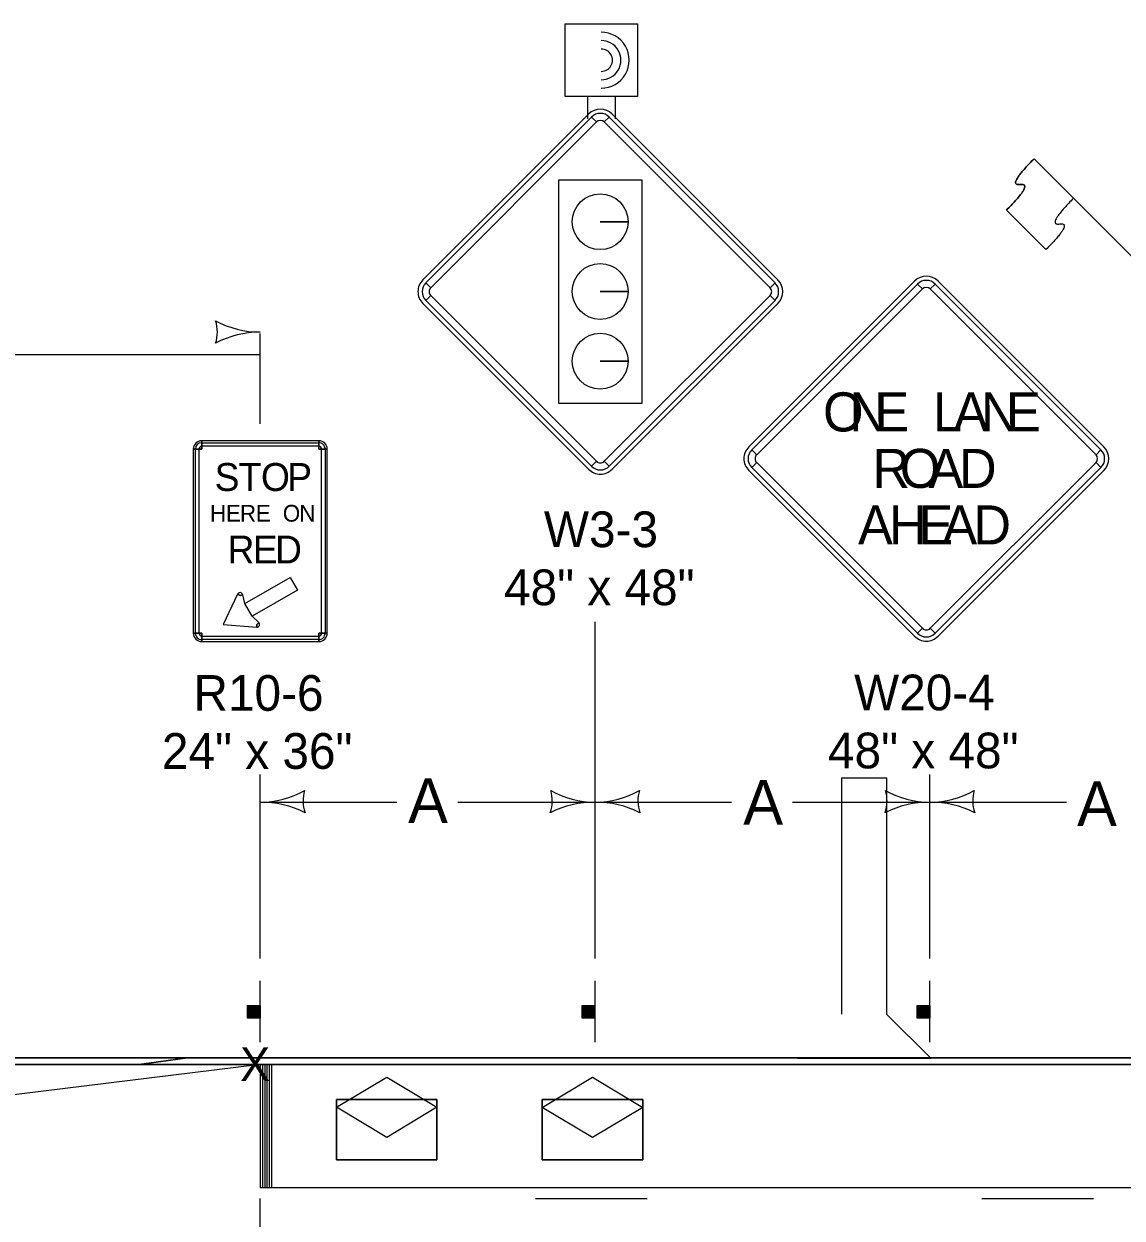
# Model space of a CAD drawing. Extents: x 10133 to 81668, y 4692 to 11018.
# Drawn here: x 23247 to 23739, y 6856 to 7391 of the extents above; entities that cross this region are included whole.
import ezdxf

# ---------------------------------------------------------------- set-up
doc = ezdxf.new("R2010")
doc.units = 0
for name, color, linetype in [('dsnCellElements', 7, 'Continuous'), ('dsnTextTabulation', 7, 'Continuous'), ('Level 5', 7, 'Continuous'), ('Level 8', 7, 'Continuous'), ('SheetAddendum', 7, 'Continuous'), ('SheetBorder', 7, 'Continuous'), ('ShtPlotIdentification', 7, 'Continuous')]:
    doc.layers.add(name, color=color, linetype=linetype)

msp = doc.modelspace()

# ---------------------------------------------------------------- linework, layer by layer
at = {"layer": 'dsnCellElements'}
for p, q in [((23499.06, 7358.55), (23499.06, 7348.55)), ((23511.56, 7358.55), (23511.56, 7348.55)), ((23352.53, 7211.87), (23352.53, 7252.28)), ((22734.47, 7242.98), (23352.53, 7242.98)), ((23502.53, 6972.3), (23502.53, 7123.21)), ((23352.53, 6972.3), (23352.53, 7054.8)), ((23652.53, 6972.3), (23652.53, 7054.8)), ((23352.53, 7042.3), (23413.7, 7042.3)), ((23441.03, 7042.3), (23502.53, 7042.3)), ((23502.53, 7042.3), (23563.7, 7042.3)), ((23591.03, 7042.3), (23652.53, 7042.3)), ((23652.53, 7042.3), (23713.7, 7042.3)), ((23352.53, 6934.8), (23352.53, 6962.3)), ((23502.53, 6934.8), (23502.53, 6962.3)), ((23652.53, 6934.8), (23652.53, 6962.3)), ((23347.2, 6945.67), (23347.2, 6951.25)), ((23347.52, 6951.25), (23347.52, 6945.67)), ((23347.75, 6945.67), (23347.75, 6951.25)), ((23348.06, 6951.25), (23348.06, 6945.67)), ((23348.29, 6945.67), (23348.27, 6951.25)), ((23348.7, 6951.25), (23348.72, 6945.67)), ((23348.93, 6945.67), (23348.93, 6951.25)), ((23349.36, 6951.25), (23349.36, 6945.67)), ((23349.73, 6945.67), (23349.73, 6951.25)), ((23350.05, 6951.25), (23350.07, 6945.67)), ((23350.28, 6945.67), (23350.28, 6951.25)), ((23350.54, 6951.25), (23350.54, 6945.67)), ((23350.88, 6945.67), (23350.88, 6951.25)), ((23351.08, 6951.25), (23351.08, 6945.67)), ((23351.31, 6945.67), (23351.31, 6951.25)), ((23351.57, 6951.25), (23351.57, 6945.67)), ((23351.83, 6945.67), (23351.83, 6951.25)), ((23352.11, 6951.25), (23352.11, 6945.67)), ((23497.2, 6945.67), (23497.2, 6951.25)), ((23497.52, 6951.25), (23497.52, 6945.67)), ((23497.75, 6945.67), (23497.75, 6951.25)), ((23498.06, 6951.25), (23498.06, 6945.67)), ((23498.29, 6945.67), (23498.27, 6951.25)), ((23498.7, 6951.25), (23498.72, 6945.67)), ((23498.93, 6945.67), (23498.93, 6951.25)), ((23499.36, 6951.25), (23499.36, 6945.67)), ((23499.73, 6945.67), (23499.73, 6951.25)), ((23500.05, 6951.25), (23500.07, 6945.67)), ((23500.28, 6945.67), (23500.28, 6951.25)), ((23500.54, 6951.25), (23500.54, 6945.67)), ((23500.88, 6945.67), (23500.88, 6951.25)), ((23501.08, 6951.25), (23501.08, 6945.67)), ((23501.31, 6945.67), (23501.31, 6951.25)), ((23501.57, 6951.25), (23501.57, 6945.67)), ((23501.83, 6945.67), (23501.83, 6951.25)), ((23502.11, 6951.25), (23502.11, 6945.67)), ((23647.2, 6945.67), (23647.2, 6951.25)), ((23647.52, 6951.25), (23647.52, 6945.67)), ((23647.75, 6945.67), (23647.75, 6951.25)), ((23648.06, 6951.25), (23648.06, 6945.67)), ((23648.29, 6945.67), (23648.27, 6951.25)), ((23648.7, 6951.25), (23648.72, 6945.67)), ((23648.93, 6945.67), (23648.93, 6951.25)), ((23649.36, 6951.25), (23649.36, 6945.67)), ((23649.73, 6945.67), (23649.73, 6951.25)), ((23650.05, 6951.25), (23650.07, 6945.67)), ((23650.28, 6945.67), (23650.28, 6951.25)), ((23650.54, 6951.25), (23650.54, 6945.67)), ((23650.88, 6945.67), (23650.88, 6951.25)), ((23651.08, 6951.25), (23651.08, 6945.67)), ((23651.31, 6945.67), (23651.31, 6951.25)), ((23651.57, 6951.25), (23651.57, 6945.67)), ((23651.83, 6945.67), (23651.83, 6951.25)), ((23652.11, 6951.25), (23652.11, 6945.67)), ((24004.98, 6924.8), (22692.53, 6924.8)), ((23352.53, 6924.8), (22864.67, 6864.81)), ((23352.53, 6924.8), (23352.53, 6869.8)), ((23353.53, 6924.8), (23353.53, 6869.8)), ((23354.53, 6924.8), (23354.53, 6869.8)), ((23355.53, 6924.8), (23355.53, 6869.8)), ((23356.53, 6924.8), (23356.53, 6869.8)), ((23357.53, 6924.8), (23357.53, 6869.8)), ((23386.69, 6882.18), (23386.69, 6909.18)), ((23386.69, 6909.18), (23431.69, 6909.18)), ((23386.69, 6882.18), (23386.69, 6909.18)), ((23386.69, 6909.18), (23431.69, 6909.18)), ((23431.69, 6909.18), (23386.69, 6909.18)), ((23386.69, 6909.18), (23386.69, 6882.18)), ((23431.69, 6882.18), (23431.69, 6909.18)), ((23431.69, 6909.18), (23431.69, 6882.18)), ((23431.69, 6882.18), (23431.69, 6909.18)), ((23478.88, 6882.1), (23478.88, 6909.1)), ((23478.88, 6909.1), (23523.88, 6909.1)), ((23478.88, 6882.1), (23478.88, 6909.1)), ((23478.88, 6909.1), (23523.88, 6909.1)), ((23523.88, 6909.1), (23478.88, 6909.1)), ((23478.88, 6909.1), (23478.88, 6882.1)), ((23523.88, 6882.1), (23523.88, 6909.1)), ((23523.88, 6909.1), (23523.88, 6882.1)), ((23523.88, 6882.1), (23523.88, 6909.1)), ((23386.69, 6882.18), (23431.69, 6882.18)), ((23431.69, 6882.18), (23386.69, 6882.18)), ((23386.69, 6882.18), (23431.69, 6882.18)), ((23478.88, 6882.1), (23523.88, 6882.1)), ((23523.88, 6882.1), (23478.88, 6882.1)), ((23478.88, 6882.1), (23523.88, 6882.1)), ((23352.53, 6627.2), (23352.53, 6864.8))]:
    msp.add_line(p, q, dxfattribs=at)
for points in [[(23489.06, 7358.55), (23489.06, 7391.05), (23521.56, 7391.05), (23521.56, 7358.55)], [(23352.43, 6951.25), (23352.43, 6945.63), (23346.81, 6945.63), (23346.81, 6951.25)], [(23502.43, 6951.25), (23502.43, 6945.63), (23496.81, 6945.63), (23496.81, 6951.25)], [(23652.43, 6951.25), (23652.43, 6945.63), (23646.81, 6945.63), (23646.81, 6951.25)]]:
    msp.add_lwpolyline(points, close=True, dxfattribs=at)
for centre, radius, start, end in [((23505.32, 7374.79), 12.5, 269.4041, 90.5445), ((23505.32, 7374.79), 12.5, 269.4041, 90.5445), ((23505.32, 7374.79), 8.75, 269.4041, 90.5445), ((23505.32, 7374.79), 5, 269.4041, 90.5445), ((23351.77, 7084.8), 42.5, 271.0176, 299.0725), ((23388.14, 7042.93), 16.42, 163.2666, 198.7334), ((23466.91, 7042.93), 16.42, 341.2666, 16.7334), ((23503.28, 7084.8), 42.5, 240.9275, 268.9824), ((23501.77, 7084.8), 42.5, 271.0176, 299.0725), ((23538.14, 7042.93), 16.42, 163.2666, 198.7334), ((23616.91, 7042.93), 16.42, 341.2666, 16.7334), ((23653.28, 7084.8), 42.5, 240.9275, 268.9824), ((23651.77, 7084.8), 42.5, 271.0176, 299.0725), ((23688.14, 7042.93), 16.42, 163.2666, 198.7334), ((23353.26, 6999.81), 42.5, 62.9275, 90.9824), ((23501.8, 6999.81), 42.5, 89.0176, 117.0725), ((23503.26, 6999.81), 42.5, 62.9275, 90.9824), ((23651.8, 6999.81), 42.5, 89.0176, 117.0725), ((23653.26, 6999.81), 42.5, 62.9275, 90.9824)]:
    msp.add_arc(centre, radius, start, end, dxfattribs=at)
at = {"layer": 'dsnTextTabulation'}
for p, q in [((23005.34, 6924.8), (23298.28, 6924.8)), ((23319.96, 6927.8), (23006.31, 6927.8)), ((23319.96, 6927.8), (23298.28, 6924.8)), ((23298.28, 6924.8), (23319.96, 6927.8)), ((23298.28, 6924.8), (23352.53, 6924.8)), ((24004.98, 6927.8), (23319.96, 6927.8)), ((23357.53, 6924.8), (24004.98, 6924.8)), ((23352.53, 6869.8), (23802.53, 6869.8)), ((23475.82, 6864.8), (23525.82, 6864.8)), ((23675.82, 6864.8), (23675.82, 6864.8)), ((23675.82, 6864.8), (23725.82, 6864.8))]:
    msp.add_line(p, q, dxfattribs=at)
for points in [[(22692.53, 6927.8), (24004.98, 6927.8)], [(22692.53, 6924.8), (24004.98, 6924.8)], [(23352.53, 6924.8), (23353.53, 6924.8), (23354.53, 6924.8)], [(23354.53, 6924.8), (23355.53, 6924.8), (23356.53, 6924.8), (23357.53, 6924.8)]]:
    msp.add_lwpolyline(points, dxfattribs=at)
at = {"layer": 'Level 5'}
msp.add_line((23686.8, 7307.59), (23704.48, 7289.92), dxfattribs=at)
for points in [[(23699.17, 7330.59), (23686.8, 7318.2), (23699.18, 7319.97), (23686.8, 7307.59)], [(23716.86, 7312.91), (23704.49, 7300.52), (23716.86, 7302.3), (23704.48, 7289.92)]]:
    msp.add_open_spline(points, degree=2, dxfattribs=at)
at = {"layer": 'Level 8'}
for centre, radius, start, end in [((23316.89, 7252.98), 16.42, 342.2666, 17.7333), ((23352.52, 7295.48), 42.5, 241.9275, 270), ((23352.52, 7210.48), 42.5, 90, 118.0725)]:
    msp.add_arc(centre, radius, start, end, dxfattribs=at)
at = {"layer": 'SheetAddendum'}
for p, q in [((23499.6, 7350.64), (23425.35, 7276.39)), ((23500.93, 7349.31), (23503.13, 7347.1)), ((23506.67, 7347.1), (23508.88, 7349.31)), ((23584.45, 7276.39), (23510.21, 7350.64)), ((23756.51, 7273.29), (23699.17, 7330.59)), ((23699.17, 7330.59), (23716.86, 7312.91)), ((23704.48, 7289.92), (23686.8, 7307.59)), ((23517.31, 7302.42), (23504.81, 7302.42)), ((23504.81, 7302.42), (23517.31, 7302.42)), ((23428.89, 7272.86), (23426.68, 7275.07)), ((23517.31, 7271.17), (23504.81, 7271.17)), ((23504.81, 7271.17), (23517.31, 7271.17)), ((23645.64, 7275.82), (23571.39, 7201.57)), ((23583.13, 7275.07), (23580.92, 7272.86)), ((23646.96, 7274.49), (23649.17, 7272.28)), ((23652.71, 7272.28), (23654.92, 7274.49)), ((23730.49, 7201.57), (23656.24, 7275.82)), ((23425.35, 7265.79), (23499.6, 7191.54)), ((23426.68, 7267.11), (23428.89, 7269.32)), ((23510.21, 7191.54), (23584.45, 7265.79)), ((23580.92, 7269.32), (23583.13, 7267.11)), ((23517.31, 7239.92), (23504.81, 7239.92)), ((23504.81, 7239.92), (23517.31, 7239.92)), ((23326.28, 7200.55), (23326.28, 7204.3)), ((23326.28, 7201.8), (23326.28, 7203.36)), ((23378.78, 7204.3), (23378.78, 7200.55)), ((23378.78, 7203.36), (23378.78, 7201.8)), ((23322.53, 7200.55), (23326.28, 7200.55)), ((23323.46, 7200.55), (23325.03, 7200.55)), ((23378.78, 7200.55), (23382.53, 7200.55)), ((23380.03, 7200.55), (23381.59, 7200.55)), ((23574.92, 7198.04), (23572.72, 7200.25)), ((23729.16, 7200.25), (23726.95, 7198.04)), ((23503.13, 7195.07), (23500.93, 7192.86)), ((23508.88, 7192.86), (23506.67, 7195.07)), ((23571.39, 7190.97), (23645.64, 7116.72)), ((23572.72, 7192.29), (23574.92, 7194.5)), ((23656.24, 7116.72), (23730.49, 7190.97)), ((23726.95, 7194.5), (23729.16, 7192.29)), ((23342.38, 7135.57), (23343.49, 7134.99)), ((23343.49, 7134.99), (23344.71, 7135.26)), ((23350.99, 7122), (23350.94, 7120.75)), ((23351.84, 7122.92), (23350.99, 7122)), ((23326.28, 7118.05), (23322.53, 7118.05)), ((23325.03, 7118.05), (23323.46, 7118.05)), ((23326.28, 7114.3), (23326.28, 7118.05)), ((23326.28, 7115.24), (23326.28, 7116.8)), ((23382.53, 7118.05), (23378.78, 7118.05)), ((23378.78, 7118.05), (23378.78, 7114.3)), ((23378.78, 7116.8), (23378.78, 7115.24)), ((23381.59, 7118.05), (23380.03, 7118.05)), ((23649.17, 7120.26), (23646.96, 7118.05)), ((23654.92, 7118.05), (23652.71, 7120.26))]:
    msp.add_line(p, q, dxfattribs=at)
for points in [[(23500.93, 7349.31), (23426.68, 7275.07), (23428.89, 7272.86), (23503.13, 7347.1), (23500.93, 7349.31)], [(23583.13, 7275.07), (23508.88, 7349.31), (23506.67, 7347.1), (23580.92, 7272.86), (23583.13, 7275.07)], [(23523.63, 7321.03), (23486.17, 7321.03), (23486.17, 7221.14), (23523.63, 7221.14), (23523.63, 7321.03)], [(23646.96, 7274.49), (23572.72, 7200.25), (23574.92, 7198.04), (23649.17, 7272.28), (23646.96, 7274.49)], [(23729.16, 7200.25), (23654.92, 7274.49), (23652.71, 7272.28), (23726.95, 7198.04), (23729.16, 7200.25)], [(23426.68, 7267.11), (23500.93, 7192.86), (23503.13, 7195.07), (23428.89, 7269.32), (23426.68, 7267.11)], [(23508.88, 7192.86), (23583.13, 7267.11), (23580.92, 7269.32), (23506.67, 7195.07), (23508.88, 7192.86)], [(23326.28, 7114.3), (23378.78, 7114.3), (23378.78, 7118.05), (23382.53, 7118.05), (23382.53, 7200.55), (23378.78, 7200.55), (23378.78, 7204.3), (23326.28, 7204.3), (23326.28, 7200.55), (23322.53, 7200.55), (23322.53, 7118.05), (23326.28, 7118.05), (23326.28, 7114.3)], [(23378.78, 7201.8), (23326.28, 7201.8), (23326.28, 7203.36), (23378.78, 7203.36), (23378.78, 7201.8)], [(23325.03, 7200.55), (23325.03, 7118.05), (23323.46, 7118.05), (23323.46, 7200.55), (23325.03, 7200.55)], [(23380.03, 7118.05), (23380.03, 7200.55), (23381.59, 7200.55), (23381.59, 7118.05), (23380.03, 7118.05)], [(23572.72, 7192.29), (23646.96, 7118.05), (23649.17, 7120.26), (23574.92, 7194.5), (23572.72, 7192.29)], [(23654.92, 7118.05), (23729.16, 7192.29), (23726.95, 7194.5), (23652.71, 7120.26), (23654.92, 7118.05)], [(23365.9, 7143.05), (23369.18, 7137.37), (23348.87, 7125.64), (23345.59, 7131.33), (23365.9, 7143.05)], [(23335.87, 7121.93), (23350.94, 7120.75), (23350.99, 7122), (23351.84, 7122.92), (23348.87, 7125.64), (23345.59, 7131.33), (23344.71, 7135.26), (23343.49, 7134.99), (23342.38, 7135.57), (23335.87, 7121.93)], [(23326.28, 7116.8), (23378.78, 7116.8), (23378.78, 7115.24), (23326.28, 7115.24), (23326.28, 7116.8)]]:
    msp.add_lwpolyline(points, close=True, dxfattribs=at)
for centre in [(23504.81, 7302.42), (23504.81, 7271.17), (23504.81, 7239.92)]:
    msp.add_circle(centre, 12.5, dxfattribs=at)
for centre, radius, start, end in [((23504.9, 7345.33), 7.5, 45, 134.9997), ((23504.9, 7345.33), 5.62, 45, 134.9997), ((23504.9, 7345.33), 2.5, 45, 134.9997), ((23650.94, 7270.52), 7.5, 45, 134.9997), ((23430.66, 7271.09), 7.5, 134.9997, 225), ((23430.66, 7271.09), 5.62, 134.9997, 225), ((23430.66, 7271.09), 2.5, 134.9997, 225), ((23579.15, 7271.09), 2.5, 315.0002, 44.9998), ((23579.15, 7271.09), 5.62, 315.0002, 44.9998), ((23579.15, 7271.09), 7.5, 315.0002, 44.9998), ((23650.94, 7270.52), 5.62, 45, 134.9997), ((23650.94, 7270.52), 2.5, 45, 134.9997), ((23326.28, 7200.55), 3.75, 90.0002, 179.9998), ((23326.28, 7200.55), 2.81, 90.0002, 179.9998), ((23326.28, 7200.55), 1.25, 90.0002, 179.9998), ((23378.78, 7200.55), 3.75, 0, 90.0002), ((23378.78, 7200.55), 2.81, 0, 90.0002), ((23378.78, 7200.55), 1.25, 0, 90.0002), ((23576.69, 7196.27), 7.5, 134.9997, 225), ((23725.18, 7196.27), 7.5, 315.0002, 44.9998), ((23576.69, 7196.27), 5.62, 134.9997, 225), ((23576.69, 7196.27), 2.5, 134.9997, 225), ((23725.18, 7196.27), 2.5, 315.0002, 44.9998), ((23725.18, 7196.27), 5.62, 315.0002, 44.9998), ((23504.9, 7196.84), 7.5, 225, 315.0002), ((23504.9, 7196.84), 5.62, 225, 315.0002), ((23504.9, 7196.84), 2.5, 225, 315.0002), ((23343.49, 7134.99), 1.25, 12.6223, 152.2756), ((23350.99, 7122), 1.25, 267.7243, 47.3776), ((23326.28, 7118.05), 3.75, 179.9998, 270.0001), ((23326.28, 7118.05), 2.81, 179.9998, 270.0001), ((23326.28, 7118.05), 1.25, 179.9998, 270.0001), ((23378.78, 7118.05), 3.75, 270.0001, 0.0003), ((23378.78, 7118.05), 2.81, 270.0001, 0.0003), ((23378.78, 7118.05), 1.25, 270.0001, 0.0003), ((23650.94, 7122.02), 7.5, 225, 315.0002), ((23650.94, 7122.02), 5.62, 225, 315.0002), ((23650.94, 7122.02), 2.5, 225, 315.0002)]:
    msp.add_arc(centre, radius, start, end, dxfattribs=at)
for points in [[(23686.8, 7307.59), (23699.18, 7319.97), (23686.8, 7318.2), (23699.17, 7330.59)], [(23716.86, 7312.91), (23704.49, 7300.52), (23716.86, 7302.3), (23704.48, 7289.92)]]:
    msp.add_open_spline(points, degree=2, dxfattribs=at)
at = {"layer": 'SheetBorder'}
for p, q in [((23613.09, 6947.42), (23613.09, 7053.29)), ((23613.09, 7053.29), (23633.09, 7053.29)), ((23633.09, 7053.29), (23633.09, 6947.42)), ((23633.09, 6947.42), (23653.03, 6927.48)), ((23653.03, 6927.48), (23593.16, 6927.6))]:
    msp.add_line(p, q, dxfattribs=at)
at = {"layer": 'ShtPlotIdentification'}
for points in [[(23386.69, 6905.69), (23409.19, 6919.19), (23431.69, 6905.69), (23409.19, 6892.19)], [(23478.88, 6905.6), (23501.38, 6919.1), (23523.88, 6905.6), (23501.38, 6892.1)]]:
    msp.add_lwpolyline(points, close=True, dxfattribs=at)

# ---------------------------------------------------------------- texts
at = {"layer": 'dsnCellElements'}
for s, height, p in [('A', 20, (23418.74, 7033)), ('A', 20, (23568.92, 7032.3)), ('A', 20, (23718.46, 7031.69)), ('X', 15, (23343.52, 6917.46))]:
    msp.add_text(s, height=height, dxfattribs=at).set_placement(p)
at = {"layer": 'SheetAddendum'}
for s, height, p in [('O', 17.5, (23604.65, 7208.46)), ('N', 17.5, (23616.43, 7208.46)), ('E', 17.5, (23627.66, 7208.46)), ('L', 17.5, (23653.91, 7208.46)), ('A', 17.5, (23663.1, 7208.46)), ('N', 17.5, (23675.37, 7208.46)), ('E', 17.5, (23686.6, 7208.46)), ('R', 17.5, (23626.76, 7183.15)), ('O', 17.5, (23639.05, 7183.15)), ('A', 17.5, (23651.89, 7183.15)), ('D', 17.5, (23665.54, 7183.15)), ('S', 12.5, (23332.08, 7181.8)), ('T', 12.5, (23342.84, 7181.8)), ('O', 12.5, (23352.83, 7181.8)), ('P', 12.5, (23364.58, 7181.8)), ('H', 7.5, (23330, 7168.05)), ('E', 7.5, (23337.15, 7168.05)), ('R', 7.5, (23343.41, 7168.05)), ('E', 7.5, (23350.56, 7168.05)), ('O', 7.5, (23362.63, 7168.05)), ('N', 7.5, (23370.01, 7168.05)), ('A', 17.5, (23620.32, 7157.83)), ('H', 17.5, (23634.19, 7157.83)), ('E', 17.5, (23647.41, 7157.83)), ('A', 17.5, (23658.12, 7157.83)), ('D', 17.5, (23671.98, 7157.83)), ('W3-3', 16, (23479.61, 7156.62)), ('R', 12.5, (23337.84, 7149.3)), ('E', 12.5, (23349.17, 7149.3)), ('D', 12.5, (23359.13, 7149.3)), ('48" x 48"', 16, (23461.73, 7130.62)), ('R10-6', 16, (23322.6, 7083.3)), ('W20-4', 16, (23618.57, 7083.52)), ('24" x 36"', 16, (23308.46, 7057.3)), ('48" x 48"', 16, (23606.87, 7057.52))]:
    msp.add_text(s, height=height, dxfattribs=at).set_placement(p)

doc.saveas('drawing.dxf')
